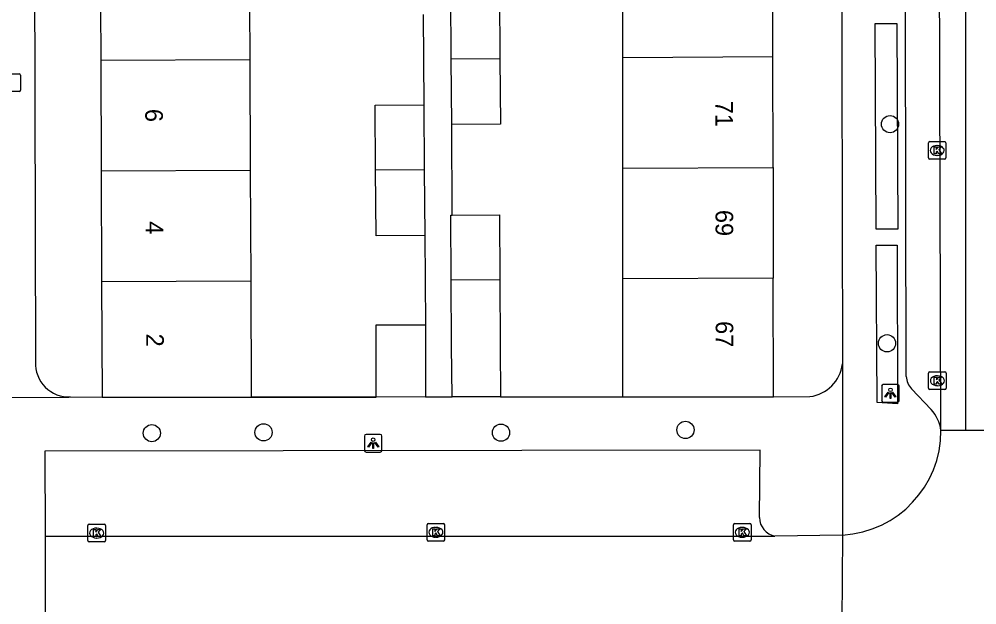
# Model space of a CAD drawing. Extents: x 160732 to 162105, y 387428 to 388479.
# Drawn here: x 161248 to 161302.4, y 388148.3 to 388181.6 of the extents above; entities that cross this region are included whole.
import ezdxf

# ---------------------------------------------------------------- set-up
doc = ezdxf.new("R2010")
doc.units = 0
for name, color, linetype in [('IMGEO_Boom', 7, 'Continuous'), ('IMGEO_Brandkraan', 7, 'Continuous'), ('IMGEO_Kolk', 7, 'Continuous'), ('IMGEO_Lichtpunt', 7, 'Continuous'), ('IMGEO_Muur', 7, 'Continuous'), ('IMGEO_Pand', 7, 'Continuous'), ('IMGEO_Pand_nummerreeks', 7, 'Continuous'), ('IMGEO_Rijbaan_lokaal_gesloten', 7, 'Continuous'), ('IMGEO_Rijbaan_lokaal_open', 7, 'Continuous'), ('IMGEO_Voetpad_open', 7, 'Continuous')]:
    doc.layers.add(name, color=color, linetype=linetype)

msp = doc.modelspace()

# ---------------------------------------------------------------- linework, layer by layer
at = {"layer": 'IMGEO_Boom'}
for centre in [(161297.475, 388175.615), (161297.304, 388163.165), (161285.843, 388158.242), (161255.501, 388158.059), (161261.852, 388158.104), (161275.353, 388158.086)]:
    msp.add_circle(centre, 0.489, dxfattribs=at)
at = {"layer": 'IMGEO_Brandkraan'}
for p, q in [((161247.104, 388178.466), (161247.956, 388178.466)), ((161248.03, 388178.392), (161248.03, 388177.54)), ((161247.956, 388177.466), (161247.104, 388177.466))]:
    msp.add_line(p, q, dxfattribs=at)
for points in [[(161247.104, 388178.466), (161247.956, 388178.466)], [(161248.03, 388178.392), (161248.03, 388177.54)], [(161247.956, 388177.466), (161247.104, 388177.466)]]:
    msp.add_lwpolyline(points, dxfattribs=at)
for centre, start, end in [((161247.954, 388178.39), 1.552, 88.448), ((161247.954, 388178.39), 1.552, 88.448), ((161247.954, 388177.542), 271.552, 358.448), ((161247.954, 388177.542), 271.552, 358.448)]:
    msp.add_arc(centre, 0.0765, start, end, dxfattribs=at)
at = {"layer": 'IMGEO_Kolk'}
for p, q in [((161299.655, 388173.694), (161299.655, 388174.546)), ((161299.73, 388174.62), (161300.582, 388174.62)), ((161300.656, 388174.546), (161300.656, 388173.694)), ((161300.143, 388174.4), (161300.168, 388174.4)), ((161300.582, 388173.62), (161299.73, 388173.62)), ((161300.166, 388173.84), (161300.141, 388173.84)), ((161299.667, 388160.61), (161299.667, 388161.462)), ((161299.742, 388161.536), (161300.594, 388161.536)), ((161300.668, 388161.462), (161300.668, 388160.61)), ((161300.155, 388161.316), (161300.18, 388161.316)), ((161300.594, 388160.536), (161299.742, 388160.536)), ((161300.178, 388160.756), (161300.153, 388160.756)), ((161251.863, 388151.955), (161251.863, 388152.807)), ((161251.938, 388152.881), (161252.79, 388152.881)), ((161252.351, 388152.661), (161252.376, 388152.661)), ((161252.864, 388152.807), (161252.864, 388151.955)), ((161271.15, 388152.001), (161271.15, 388152.853)), ((161271.225, 388152.927), (161272.077, 388152.927)), ((161271.638, 388152.707), (161271.663, 388152.707)), ((161272.151, 388152.853), (161272.151, 388152.001)), ((161288.573, 388152), (161288.573, 388152.852)), ((161288.648, 388152.926), (161289.5, 388152.926)), ((161289.061, 388152.706), (161289.086, 388152.706)), ((161289.574, 388152.852), (161289.574, 388152)), ((161252.374, 388152.101), (161252.349, 388152.101)), ((161271.661, 388152.147), (161271.636, 388152.147)), ((161289.084, 388152.146), (161289.059, 388152.146)), ((161252.79, 388151.881), (161251.938, 388151.881)), ((161272.077, 388151.927), (161271.225, 388151.927)), ((161289.5, 388151.926), (161288.648, 388151.926))]:
    msp.add_line(p, q, dxfattribs=at)
for points in [[(161299.655, 388173.694), (161299.655, 388174.546)], [(161299.73, 388174.62), (161300.582, 388174.62)], [(161300.656, 388174.546), (161300.656, 388173.694)], [(161299.976, 388174.32), (161300.099, 388174.32), (161300.099, 388174.169), (161300.229, 388174.32), (161300.393, 388174.32), (161300.247, 388174.169), (161300.4, 388173.92), (161300.248, 388173.92), (161300.163, 388174.084), (161300.099, 388174.017), (161300.099, 388173.92), (161299.976, 388173.92), (161299.976, 388174.32)], [(161300.582, 388173.62), (161299.73, 388173.62)], [(161299.667, 388160.61), (161299.667, 388161.462)], [(161299.742, 388161.536), (161300.594, 388161.536)], [(161300.668, 388161.462), (161300.668, 388160.61)], [(161299.988, 388161.236), (161300.111, 388161.236), (161300.111, 388161.085), (161300.241, 388161.236), (161300.405, 388161.236), (161300.259, 388161.085), (161300.412, 388160.836), (161300.26, 388160.836), (161300.175, 388161), (161300.111, 388160.933), (161300.111, 388160.836), (161299.988, 388160.836), (161299.988, 388161.236)], [(161300.594, 388160.536), (161299.742, 388160.536)], [(161251.863, 388151.955), (161251.863, 388152.807)], [(161251.938, 388152.881), (161252.79, 388152.881)], [(161252.864, 388152.807), (161252.864, 388151.955)], [(161271.15, 388152.001), (161271.15, 388152.853)], [(161271.225, 388152.927), (161272.077, 388152.927)], [(161271.471, 388152.627), (161271.594, 388152.627), (161271.594, 388152.476), (161271.724, 388152.627), (161271.888, 388152.627), (161271.742, 388152.476), (161271.895, 388152.227), (161271.743, 388152.227), (161271.658, 388152.391), (161271.594, 388152.324), (161271.594, 388152.227), (161271.471, 388152.227), (161271.471, 388152.627)], [(161272.151, 388152.853), (161272.151, 388152.001)], [(161288.573, 388152), (161288.573, 388152.852)], [(161288.648, 388152.926), (161289.5, 388152.926)], [(161288.894, 388152.626), (161289.017, 388152.626), (161289.017, 388152.475), (161289.147, 388152.626), (161289.311, 388152.626), (161289.165, 388152.475), (161289.318, 388152.226), (161289.166, 388152.226), (161289.081, 388152.39), (161289.017, 388152.323), (161289.017, 388152.226), (161288.894, 388152.226), (161288.894, 388152.626)], [(161289.574, 388152.852), (161289.574, 388152)], [(161252.184, 388152.581), (161252.307, 388152.581), (161252.307, 388152.43), (161252.437, 388152.581), (161252.601, 388152.581), (161252.455, 388152.43), (161252.608, 388152.181), (161252.456, 388152.181), (161252.371, 388152.345), (161252.307, 388152.278), (161252.307, 388152.181), (161252.184, 388152.181), (161252.184, 388152.581)], [(161252.79, 388151.881), (161251.938, 388151.881)], [(161272.077, 388151.927), (161271.225, 388151.927)], [(161289.5, 388151.926), (161288.648, 388151.926)]]:
    msp.add_lwpolyline(points, dxfattribs=at)
for centre, start, end in [((161299.732, 388174.544), 91.552, 178.448), ((161299.732, 388174.544), 91.552, 178.448), ((161300.58, 388174.544), 1.552, 88.448), ((161300.58, 388174.544), 1.552, 88.448), ((161299.732, 388173.696), 181.552, 268.448), ((161299.732, 388173.696), 181.552, 268.448), ((161300.58, 388173.696), 271.552, 358.448), ((161300.58, 388173.696), 271.552, 358.448), ((161299.744, 388161.46), 91.552, 178.448), ((161299.744, 388161.46), 91.552, 178.448), ((161300.592, 388161.46), 1.552, 88.448), ((161300.592, 388161.46), 1.552, 88.448), ((161299.744, 388160.612), 181.552, 268.448), ((161299.744, 388160.612), 181.552, 268.448), ((161300.592, 388160.612), 271.552, 358.448), ((161300.592, 388160.612), 271.552, 358.448), ((161251.94, 388152.805), 91.552, 178.448), ((161251.94, 388152.805), 91.552, 178.448), ((161252.788, 388152.805), 1.552, 88.448), ((161252.788, 388152.805), 1.552, 88.448), ((161271.227, 388152.851), 91.552, 178.448), ((161271.227, 388152.851), 91.552, 178.448), ((161272.075, 388152.851), 1.552, 88.448), ((161272.075, 388152.851), 1.552, 88.448), ((161288.65, 388152.85), 91.552, 178.448), ((161288.65, 388152.85), 91.552, 178.448), ((161289.498, 388152.85), 1.552, 88.448), ((161289.498, 388152.85), 1.552, 88.448), ((161251.94, 388151.957), 181.552, 268.448), ((161251.94, 388151.957), 181.552, 268.448), ((161252.788, 388151.957), 271.552, 358.448), ((161252.788, 388151.957), 271.552, 358.448), ((161271.227, 388152.003), 181.552, 268.448), ((161271.227, 388152.003), 181.552, 268.448), ((161272.075, 388152.003), 271.552, 358.448), ((161272.075, 388152.003), 271.552, 358.448), ((161288.65, 388152.002), 181.552, 268.448), ((161288.65, 388152.002), 181.552, 268.448), ((161289.498, 388152.002), 271.552, 358.448), ((161289.498, 388152.002), 271.552, 358.448)]:
    msp.add_arc(centre, 0.0765, start, end, dxfattribs=at)
for centre, major_axis, ratio, start_param, end_param in [((161300.142, 388174.12), (-0.387, 0.002), 0.722429, 4.712389, 7.853982), ((161300.167, 388174.12), (-0.39, 0.002), 0.717154, 1.570796, 4.712389), ((161300.154, 388161.036), (-0.387, 0.002), 0.722429, 4.712389, 7.853982), ((161300.179, 388161.036), (-0.39, 0.002), 0.717154, 1.570796, 4.712389), ((161252.35, 388152.381), (-0.387, 0.002), 0.722429, 4.712389, 7.853982), ((161252.375, 388152.381), (-0.39, 0.002), 0.717154, 1.570796, 4.712389), ((161271.637, 388152.427), (-0.387, 0.002), 0.722429, 4.712389, 7.853982), ((161271.662, 388152.427), (-0.39, 0.002), 0.717154, 1.570796, 4.712389), ((161289.06, 388152.426), (-0.387, 0.002), 0.722429, 4.712389, 7.853982), ((161289.085, 388152.426), (-0.39, 0.002), 0.717154, 1.570796, 4.712389)]:
    msp.add_ellipse(centre, major_axis=major_axis, ratio=ratio, start_param=start_param, end_param=end_param, dxfattribs=at)
at = {"layer": 'IMGEO_Lichtpunt'}
for p, q in [((161297.902, 388160.819), (161297.094, 388160.819)), ((161297.902, 388160.819), (161297.094, 388160.819)), ((161297, 388160.724), (161297, 388159.917)), ((161297, 388160.724), (161297, 388159.917)), ((161297.996, 388159.917), (161297.996, 388160.724)), ((161297.996, 388159.917), (161297.996, 388160.724)), ((161297.094, 388159.823), (161297.902, 388159.823)), ((161297.094, 388159.823), (161297.902, 388159.823)), ((161267.589, 388157.887), (161267.589, 388157.08)), ((161267.589, 388157.887), (161267.589, 388157.08)), ((161268.491, 388157.982), (161267.683, 388157.982)), ((161268.491, 388157.982), (161267.683, 388157.982)), ((161268.585, 388157.08), (161268.585, 388157.887)), ((161268.585, 388157.08), (161268.585, 388157.887)), ((161267.683, 388156.986), (161268.491, 388156.986)), ((161267.683, 388156.986), (161268.491, 388156.986))]:
    msp.add_line(p, q, dxfattribs=at)
for points in [[(161297.374, 388160.388), (161297.413, 388160.36), (161297.225, 388160.098), (161297.187, 388160.125), (161297.374, 388160.388)], [(161297.476, 388160.34), (161297.523, 388160.34), (161297.523, 388160.018), (161297.476, 388160.018), (161297.476, 388160.34)], [(161297.586, 388160.36), (161297.624, 388160.387), (161297.811, 388160.125), (161297.772, 388160.097), (161297.586, 388160.36)], [(161267.963, 388157.551), (161268.002, 388157.523), (161267.814, 388157.261), (161267.776, 388157.288), (161267.963, 388157.551)], [(161268.175, 388157.523), (161268.213, 388157.55), (161268.4, 388157.288), (161268.361, 388157.26), (161268.175, 388157.523)], [(161268.065, 388157.503), (161268.112, 388157.503), (161268.112, 388157.181), (161268.065, 388157.181), (161268.065, 388157.503)]]:
    msp.add_lwpolyline(points, dxfattribs=at)
for centre in [(161297.499, 388160.522), (161268.088, 388157.685)]:
    msp.add_circle(centre, 0.0994, dxfattribs=at)
for centre, start, end in [((161297.094, 388160.724), 90, 180), ((161297.094, 388160.724), 90, 180), ((161297.902, 388160.724), 0, 90), ((161297.902, 388160.724), 0, 90), ((161297.094, 388159.917), 180, 270), ((161297.094, 388159.917), 180, 270), ((161297.902, 388159.917), 270, 0), ((161297.902, 388159.917), 270, 360), ((161267.683, 388157.887), 90, 180), ((161267.683, 388157.887), 90, 180), ((161268.491, 388157.887), 0, 90), ((161268.491, 388157.887), 0, 90), ((161267.683, 388157.08), 180, 270), ((161267.683, 388157.08), 180, 270), ((161268.491, 388157.08), 270, 0), ((161268.491, 388157.08), 270, 360)]:
    msp.add_arc(centre, 0.0946, start, end, dxfattribs=at)
at = {"layer": 'IMGEO_Muur'}
for points in [[(161268.255, 388160.112), (161261.154, 388160.106)], [(161275.33, 388160.114), (161282.277, 388160.124)]]:
    msp.add_lwpolyline(points, dxfattribs=at)
at = {"layer": 'IMGEO_Pand'}
for points in [[(161252.565, 388185.535), (161252.592, 388179.23)], [(161261.043, 388185.575), (161261.071, 388179.275)], [(161282.282, 388179.385), (161282.284, 388185.675)], [(161290.82, 388179.43), (161290.811, 388185.715)], [(161272.503, 388183.017), (161275.271, 388183.036), (161275.295, 388179.348)], [(161272.527, 388179.334), (161272.503, 388183.017)], [(161272.527, 388179.334), (161275.295, 388179.348)], [(161272.552, 388175.595), (161272.527, 388179.334)], [(161275.295, 388179.348), (161275.32, 388175.613), (161272.552, 388175.595)], [(161282.28, 388173.105), (161282.282, 388179.385)], [(161290.82, 388179.43), (161282.282, 388179.385)], [(161290.829, 388173.145), (161290.82, 388179.43)], [(161261.071, 388179.275), (161252.592, 388179.23)], [(161252.592, 388179.23), (161252.62, 388172.965)], [(161261.071, 388179.275), (161261.098, 388173.005)], [(161268.225, 388173.019), (161268.2, 388176.697), (161270.968, 388176.716)], [(161270.968, 388176.716), (161270.993, 388173.032)], [(161252.62, 388172.965), (161261.098, 388173.005)], [(161252.62, 388172.965), (161252.647, 388166.67)], [(161261.098, 388173.005), (161261.126, 388166.712)], [(161268.225, 388173.019), (161270.993, 388173.032)], [(161271.017, 388169.293), (161268.249, 388169.275), (161268.225, 388173.019)], [(161270.993, 388173.032), (161271.017, 388169.293)], [(161282.278, 388166.818), (161282.28, 388173.105)], [(161282.28, 388173.105), (161290.829, 388173.145)], [(161290.829, 388173.145), (161290.839, 388166.86)], [(161272.523, 388166.77), (161272.499, 388170.45), (161272.587, 388170.451)], [(161272.587, 388170.451), (161275.267, 388170.469), (161275.291, 388166.784)], [(161272.523, 388166.77), (161275.291, 388166.784)], [(161275.291, 388166.784), (161275.316, 388163.046), (161275.33, 388160.114)], [(161282.277, 388160.124), (161282.278, 388166.818)], [(161290.839, 388166.86), (161282.278, 388166.818)], [(161290.848, 388160.124), (161290.839, 388166.86)], [(161252.647, 388166.67), (161261.126, 388166.712)], [(161252.647, 388166.67), (161252.675, 388160.099)], [(161261.126, 388166.712), (161261.154, 388160.106)], [(161272.575, 388160.12), (161272.548, 388163.028), (161272.523, 388166.77)], [(161268.255, 388160.112), (161268.263, 388164.217), (161271.06, 388164.211)], [(161271.06, 388164.211), (161271.052, 388160.114)], [(161252.675, 388160.099), (161261.154, 388160.106)], [(161271.052, 388160.114), (161268.255, 388160.112)], [(161275.33, 388160.114), (161272.575, 388160.12)], [(161282.277, 388160.124), (161290.848, 388160.124)]]:
    msp.add_lwpolyline(points, dxfattribs=at)
at = {"layer": 'IMGEO_Rijbaan_lokaal_gesloten'}
for points in [[(161301.782, 388158.214), (161301.782, 388213.646)], [(161300.369, 388158.214), (161300.224, 388205.096)], [(161301.782, 388158.214), (161300.369, 388158.214)], [(161305.369, 388158.215), (161301.782, 388158.214)]]:
    msp.add_lwpolyline(points, dxfattribs=at)
at = {"layer": 'IMGEO_Rijbaan_lokaal_open'}
for points in [[(161249.439, 388152.199), (161249.429, 388147.206)], [(161249.439, 388152.199), (161290.928, 388152.206)], [(161294.781, 388152.269), (161290.928, 388152.206)], [(161294.781, 388152.269), (161294.744, 388147.33)]]:
    msp.add_lwpolyline(points, dxfattribs=at)
msp.add_arc((161294.437, 388158.191), 5.932, 273.3265, 0.2195, dxfattribs=at)
at = {"layer": 'IMGEO_Voetpad_open'}
for points in [[(161294.685, 388204.624), (161294.766, 388161.993)], [(161298.4, 388161.281), (161298.318, 388202.127)], [(161249.834, 388192.141), (161249.537, 388192.108), (161248.813, 388192.106), (161248.886, 388162.102)], [(161270.925, 388181.84), (161270.968, 388176.716)], [(161296.691, 388169.644), (161296.636, 388181.331), (161297.856, 388181.336), (161297.911, 388169.649), (161296.691, 388169.644)], [(161272.587, 388170.451), (161272.552, 388175.595)], [(161271.017, 388169.293), (161271.06, 388164.211)], [(161296.737, 388159.794), (161296.695, 388168.738), (161297.887, 388168.739), (161297.909, 388159.724), (161296.737, 388159.794)], [(161294.766, 388161.993), (161294.781, 388152.269)], [(161299.812, 388159.405), (161298.704, 388160.573)], [(161244.065, 388160.078), (161250.777, 388160.108), (161250.871, 388160.115)], [(161250.871, 388160.115), (161252.675, 388160.099)], [(161261.154, 388160.106), (161268.255, 388160.112)], [(161271.052, 388160.114), (161272.575, 388160.12)], [(161275.33, 388160.114), (161282.277, 388160.124)], [(161290.848, 388160.124), (161292.916, 388160.14)], [(161290.047, 388153.264), (161290.091, 388157.088), (161249.407, 388157.043), (161249.439, 388152.199)]]:
    msp.add_lwpolyline(points, dxfattribs=at)
for centre, radius, start, end in [((161250.786, 388162.015), 1.902, 177.3678, 272.5745), ((161292.655, 388162.25), 2.127, 277.0477, 353.0452), ((161299.424, 388161.301), 1.024, 181.1364, 225.3389), ((161298.151, 388157.902), 2.24, 7.9956, 42.133), ((161291.145, 388153.283), 1.098, 180.9722, 258.5963)]:
    msp.add_arc(centre, radius, start, end, dxfattribs=at)

# ---------------------------------------------------------------- texts
at = {"layer": 'IMGEO_Pand_nummerreeks'}
for s, rotation, p in [('71', 270.0842, (161287.544, 388176.944)), ('6', 270.2495, (161255.124, 388176.479)), ('69', 270.0842, (161287.553, 388170.741)), ('4', 270.2495, (161255.152, 388170.095)), ('67', 270.0842, (161287.562, 388164.425)), ('2', 270.2495, (161255.18, 388163.713))]:
    msp.add_text(s, height=1, rotation=rotation, dxfattribs=at).set_placement(p)

doc.saveas('drawing.dxf')
